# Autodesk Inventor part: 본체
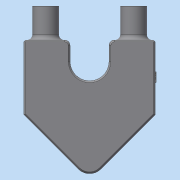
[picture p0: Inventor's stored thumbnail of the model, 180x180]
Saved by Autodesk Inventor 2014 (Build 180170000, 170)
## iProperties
Created: 2025-02
Part Number: 본체
Material: 일반
Document SubType Name: Modeling
Designer: dg
Density: 1 g/cm^3
Appearance: 기본값
Mass: 272.94 g
Surface Area: 337.231 cm^2
Volume: 272.94 cm^3
Author: dg
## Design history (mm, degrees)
sketch "스케치1"
  geometry: L1 (-37, 21)-(37, 21); L2 (37, 21)-(37, -21); L3 (37, -21)-(-37, -21); L4 (-37, -21)-(-37, 21); L5 (-37, -21)-(0, -58); L6 (0, -58)-(37, -21); 3 further points
  constraints: 12 end point, 2 midpoint, 2 parallel, 2 vertical alignment, 1 horizontal, 1 horizontal alignment, 1 perpendicular
  dimensions: "d0" = 90 deg angle of L6 L5; "d1" = 42 distance of L3.end L1.start; "d2" = 74 distance of L1.start L1.end
extrude "돌출1" new body sketch "스케치1" distance "d3" = 74; taper "d4" = 0 deg
node "작업 평면1"
sketch "스케치2"
  geometry: L1 (0, -58)-(-37, -21) reference; L2 (37, -21)-(0, -58) reference; L3 (-37, -21)-(-37, 21) reference; L4 (37, 21)-(37, -21) reference; L5 (-37, -16.757)-(0, -53.757); L6 (0, -53.757)-(37, -16.757); 1 further point
  constraints: 4 end point, 2 perpendicular, 2 point on line
  dimensions: "d5" = 90 deg angle of L6 L5; "d101" = 3 distance between parallel lines of L1 L5
extrude "돌출2" cut sketch "스케치2" stored distance "d7" = 36; taper "d8" = 0 deg
sketch "스케치3"
  geometry: L1 (37, 21)-(-37, 21) reference; L2 (-11, 9)-(-11, 21); L3 (11, 9)-(11, 21); A1 r 11 centre (0, 9) between (-11, 9) and (11, 9); 1 further point
  constraints: 4 end point, 2 perpendicular, 2 point on circle, 2 point on line, 2 tangent, 1 centre point, 1 vertical alignment
  dimensions: "d9" = 22 diameter of A1; "d10" = 12 distance from line of L1 A1.centre
extrude "돌출3" cut sketch "스케치3" stored distance "d11" = 36; taper "d12" = 0 deg
sketch "스케치4"
  geometry: L1 (0, -53.757)-(-37, -16.757) reference; L2 (-37, -16.757)-(-37, 21) reference; L3 (-37, 21)-(-11, 21) reference; L4 (-11, 21)-(-11, 9) reference; L5 (11, 9)-(11, 21) reference; L6 (11, 21)-(37, 21) reference; L7 (37, 21)-(37, -16.757) reference; L8 (37, -16.757)-(0, -53.757) reference; L9 (-37, 7)-(-23, 21); L10 (23, 21)-(37, 7); A1 r 11 centre (0, 9) between (-11, 9) and (11, 9) reference; 1 further point
  constraints: 4 end point, 4 point on line, 1 parallel, 1 perpendicular
  dimensions: "d13" = 14 distance from line of L3 L9.start; "d14" = 14 distance of L10.end L6.end
extrude "돌출4" cut sketch "스케치4" stored distance "d15" = 20; taper "d16" = 0 deg
sketch "스케치5"
  geometry: L1 (-19.799, 0)-(-19.799, 20) reference; C1 r 6.5 at (-9.899, 10); 3 further points
  constraints: 1 centre point, 1 horizontal alignment, 1 midpoint, 1 vertical alignment
  dimensions: "d17" = 13 diameter of C1
extrude "돌출5" cut sketch "스케치5" distance "d18" = 3; taper "d19" = 0 deg
sketch "스케치6"
  geometry: L1 (12, -47)-(12, -27) reference; C1 r 21 at (-11, -37); 2 further points
  constraints: 1 centre point, 1 horizontal alignment, 1 midpoint, 1 vertical alignment
  dimensions: "d20" = 42 diameter of C1
extrude "돌출6" cut sketch "스케치6" distance "d21" = 8; taper "d22" = 0 deg
hole "구멍1" diameter "d25" = 32; stored, may be unused: countersink angle "d29" = 90 deg, drill point angle "d31" = 0 deg; dims "d23" = 10, "d24" = 10, "d26" = 6, "d27" = 4, "d28" = 2, "d30" = 20
hole "구멍2" diameter "d34" = 8; stored, may be unused: countersink angle "d38" = 90 deg, drill point angle "d40" = 0 deg; dims "d32" = 10, "d33" = 10, "d35" = 6, "d36" = 4, "d37" = 2, "d39" = 20
sketch "스케치7"
  geometry: L1 (-11, -37)-(10, -37); L2 (-35.749, -61.749)-(13.749, -12.251); C1 r 7.5 at (13.749, -12.251); C2 r 7.5 at (-35.749, -61.749); A1 r 21 centre (-11, -37) between (0, -54.889) and (0, -19.111) reference; A2 r 35 centre (-11, -37) between (13.749, -12.251) and (-35.749, -61.749); 1 further point
  constraints: 4 end point, 3 centre point, 3 coincident, 3 point on circle, 1 midpoint
  dimensions: "d42" = 70 diameter of A2; "d43" = 45 deg angle of L1 L2; "d44" = 15 diameter of C1; "d45" = 15 diameter of C2
extrude "돌출7" join sketch "스케치7" distance "d46" = 19; taper "d47" = 0 deg
hole "구멍3" diameter "d50" = 4.917; stored, may be unused: countersink angle "d54" = 90 deg, drill point angle "d56" = 118 deg; dims "d48" = 10, "d49" = 10, "d51" = 12, "d52" = 4, "d53" = 2, "d55" = 14
hole "구멍4" diameter "d59" = 4.917; stored, may be unused: countersink angle "d63" = 90 deg, drill point angle "d65" = 118 deg; dims "d57" = 10, "d58" = 10, "d60" = 12, "d61" = 4, "d62" = 2, "d64" = 14
chamfer "모따기1" distance "d66" = 1; stored, may be unused: second distance "d67" = 2, angle "d68" = 45 deg
fillet "모깎기1" dims "d69" = 6
fillet "모깎기2" dims "d70" = 9
chamfer "모따기2" distance "d71" = 1; stored, may be unused: second distance "d72" = 2, angle "d73" = 45 deg
chamfer "모따기3" distance "d74" = 1; stored, may be unused: second distance "d75" = 2, angle "d76" = 45 deg
fillet "모깎기3" dims "d77" = 3
fillet "모깎기4" dims "d78" = 3
chamfer "모따기4" distance "d79" = 1; stored, may be unused: second distance "d80" = 2, angle "d81" = 45 deg
chamfer "모따기5" distance "d82" = 1; stored, may be unused: second distance "d83" = 2, angle "d84" = 45 deg
fillet "모깎기5" dims "d85" = 3
chamfer "모따기6" distance "d86" = 1; stored, may be unused: second distance "d87" = 2, angle "d88" = 45 deg
chamfer "모따기7" distance "d89" = 1; stored, may be unused: second distance "d90" = 2, angle "d91" = 45 deg
sketch "스케치8"
  geometry: L1 (28, 23.757)-(8, 23.757) reference; L2 (50.249, 56.757)-(35.249, 56.757) reference; 3 further points
  constraints: 1 midpoint, 1 vertical alignment, 1 other
  dimensions: "d92" = 40 distance from line of point (18, 16.757) L2
feature "엠보싱1" sketch "스케치8" dims "d0" = 90 deg, "d1" = 42, "d2" = 74, "d93" = 0.5, "d94" = 0
chamfer "모따기8" distance "d95" = 1; stored, may be unused: second distance "d96" = 2, angle "d97" = 45 deg
chamfer "모따기9" distance "d98" = 1; stored, may be unused: second distance "d99" = 2, angle "d100" = 45 deg
node "솔리드1"
mirror "대칭1"
node "절단 모서리 투영1"
